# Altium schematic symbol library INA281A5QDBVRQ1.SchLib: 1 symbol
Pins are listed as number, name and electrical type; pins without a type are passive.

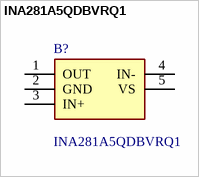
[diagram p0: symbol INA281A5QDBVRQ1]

## INA281A5QDBVRQ1
designator B?
Current Sense Amplifiers Automotive AEC-Q100, -4-V to 110-V, 1.3-MHz current sense amplifier 5-SOT-23 -40 to 125; Manufacturer_Name: Texas Instruments; Geometry.Height: 1.45mm
footprint SOT95P280X145-5N
pins: 1 OUT, 2 GND, 3 IN+, 4 IN-, 5 VS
